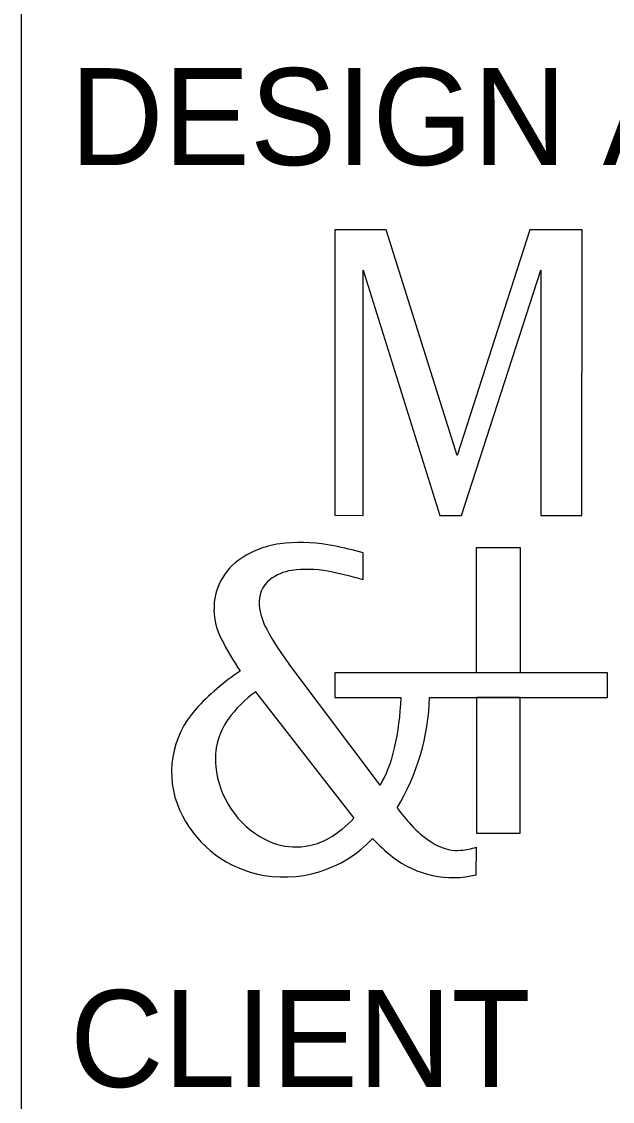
# Model space of a CAD drawing. Extents: x -32.9 to 34, y 0 to 22.3.
# Drawn here: x 32 to 32.61, y 3.384 to 4.498 of the extents above; entities that cross this region are included whole.
import ezdxf

# ---------------------------------------------------------------- set-up
doc = ezdxf.new("R2010")
doc.units = 0
for name, color, linetype in [('PF_X_Ground_Line', 7, 'Continuous'), ('PV_P_Curb_Ramp', 7, 'Continuous'), ('PV_P_Saw_Cut_Line', 7, 'Continuous')]:
    doc.layers.add(name, color=color, linetype=linetype)

msp = doc.modelspace()

# ---------------------------------------------------------------- linework, layer by layer
at = {"layer": 'PV_P_Curb_Ramp'}
msp.add_line((32, 0.5), (32, 21.5), dxfattribs=at)
at = {"layer": 'PV_P_Saw_Cut_Line'}
for p, q in [((32.3525, 3.922), (32.3525, 3.9497)), ((32.4696, 3.8261), (32.4697, 3.9552)), ((32.4697, 3.9552), (32.5147, 3.9552)), ((32.5147, 3.9552), (32.5146, 3.8261)), ((32.37, 3.7101), (32.2762, 3.8349)), ((32.2416, 3.8065), (32.3429, 3.6759)), ((32.4696, 3.8006), (32.4696, 3.6605)), ((32.5146, 3.8006), (32.4696, 3.8006)), ((32.5145, 3.6605), (32.5146, 3.8006)), ((32.1797, 3.7884), (32.18, 3.7887)), ((32.4696, 3.6605), (32.5145, 3.6605)), ((32.4694, 3.6176), (32.4695, 3.646))]:
    msp.add_line(p, q, dxfattribs=at)
msp.add_lwpolyline([(32.3526, 3.9885), (32.3527, 4.2417), (32.4317, 3.9885), (32.4542, 3.9885), (32.536, 4.2417), (32.5359, 3.9885), (32.5784, 3.9885), (32.5785, 4.2831), (32.5246, 4.2831), (32.4495, 4.0504), (32.3765, 4.2832), (32.3235, 4.2832), (32.3234, 3.9886)], close=True, dxfattribs=at)
msp.add_lwpolyline([(32.3526, 3.9885), (32.3527, 4.2417), (32.4317, 3.9885), (32.4542, 3.9885), (32.536, 4.2417), (32.5359, 3.9885), (32.5784, 3.9885), (32.5785, 4.2831), (32.5246, 4.2831), (32.4495, 4.0504), (32.3765, 4.2832), (32.3235, 4.2832), (32.3234, 3.9886)], close=True, dxfattribs=at)
msp.add_lwpolyline([(32.4211, 3.8006), (32.6049, 3.8006), (32.6049, 3.8261), (32.3233, 3.8261), (32.3233, 3.8007), (32.3916, 3.8006)], dxfattribs=at)
for centre, radius, start, end in [((32.2803, 3.862), 0.0981, 94.5206, 123.1061), ((32.2871, 3.7753), 0.1851, 79.0563, 94.5206), ((32.2546, 3.6069), 0.3566, 74.0516, 79.0563), ((32.2606, 3.8922), 0.062, 123.1061, 181.2152), ((32.2855, 3.8851), 0.0471, 98.3723, 128.329), ((32.2951, 3.8196), 0.1132, 79.2666, 98.3723), ((32.2495, 3.579), 0.3581, 73.2803, 79.2666), ((32.2746, 3.8989), 0.0295, 128.329, 186.0821), ((32.2669, 3.8924), 0.0684, 181.2152, 207.1091), ((32.3115, 3.9028), 0.0666, 186.0821, 208.5769), ((32.5116, 4.0118), 0.2945, 208.5769, 216.933), ((32.517, 4.0204), 0.3493, 207.1091, 213.4656), ((32.3628, 3.6213), 0.2479, 123.6, 137.6035), ((32.3108, 3.7092), 0.1194, 125.3927, 144.9042), ((32.1831, 3.8084), 0.2382, 329.2356, 358.1314), ((32.2512, 3.7236), 0.0964, 137.6035, 203.9313), ((32.2717, 3.7366), 0.0717, 144.9042, 185.7554), ((32.2959, 3.7391), 0.096, 185.7554, 242.1528), ((32.2691, 3.7316), 0.116, 203.9313, 256.6813), ((32.5828, 3.8332), 0.2441, 216.933, 222.2898), ((32.2633, 3.7491), 0.1081, 299.979, 317.3992), ((32.4823, 3.7418), 0.1082, 222.2898, 236.5762), ((32.271, 3.7399), 0.1246, 256.6813, 317.1089), ((32.2831, 3.7148), 0.0685, 242.1528, 299.979), ((32.487, 3.7702), 0.1697, 222.685, 232.3525), ((32.453, 3.6975), 0.0551, 236.5762, 256.9728), ((32.4497, 3.6832), 0.0405, 256.9728, 275.0638), ((32.446, 3.7257), 0.0831, 275.0638, 286.4619), ((32.4453, 3.7161), 0.1014, 232.3525, 283.7629)]:
    msp.add_arc(centre, radius, start, end, dxfattribs=at)
msp.add_ellipse((32.351, 3.8018), major_axis=(-0.0031, -0.1077), ratio=0.377453, start_param=0.562501, end_param=1.570796, dxfattribs=at)

# ---------------------------------------------------------------- texts
at = {"layer": 'PF_X_Ground_Line'}
msp.add_text('CLIENT', height=0.1, dxfattribs=at).set_placement((32.05, 3.3986))
at = {"layer": 'PV_P_Saw_Cut_Line'}
msp.add_text('DESIGN AGENCY', height=0.1, dxfattribs=at).set_placement((32.05, 4.35))

doc.saveas('drawing.dxf')
